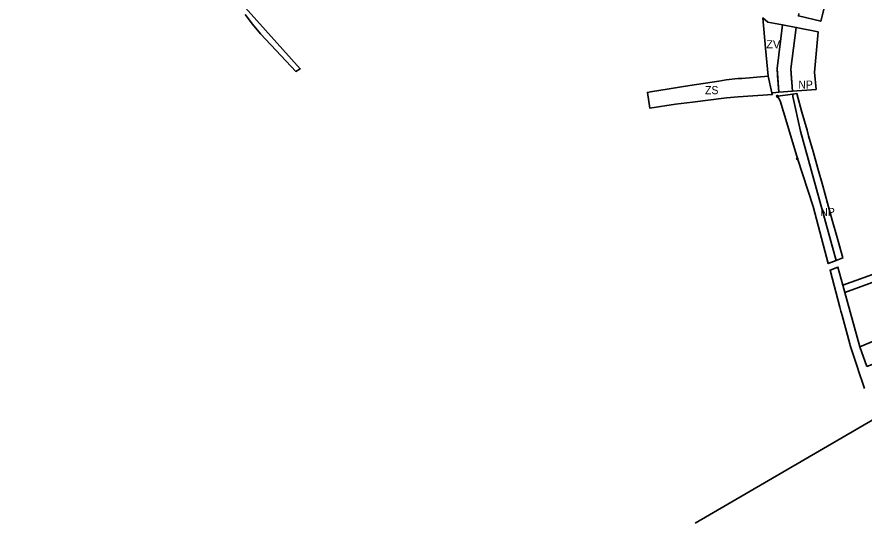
# Model space of a CAD drawing. Extents: x -650276 to -642489, y -1074311 to -1066658.
# Drawn here: x -650258 to -649019, y -1071012 to -1070272 of the extents above; entities that cross this region are included whole.
import ezdxf

# ---------------------------------------------------------------- set-up
doc = ezdxf.new("R2010")
doc.units = 0
doc.header["$LTSCALE"] = 4.8
doc.header["$PDMODE"] = 32
doc.header["$PDSIZE"] = 2.4
for name, color, linetype, lineweight in [('24', 7, 'Continuous', 35), ('40', 7, 'Continuous', 35), ('41', 7, 'Continuous', 35), ('48', 7, 'Continuous', 35), ('54', 7, 'Continuous', 35)]:
    doc.layers.add(name, color=color, linetype=linetype, lineweight=lineweight)
doc.layers.add('62', color=7, linetype='Continuous')

msp = doc.modelspace()

# ---------------------------------------------------------------- linework, layer by layer
at = {"layer": '24'}
msp.add_line((-649146.163, -1070347.543), (-649145.424, -1070357.637), dxfattribs=at)
for points in [[(-649138.43, -1070283.6), (-649146.163, -1070347.543), (-649146.163, -1070347.543), (-649145.424, -1070357.637)], [(-649125.503, -1070355.837), (-649126.069, -1070348.097), (-649118.257, -1070287.455), (-649138.43, -1070283.6), (-649146.163, -1070347.543)], [(-649125.503, -1070355.837), (-649126.069, -1070348.097), (-649118.257, -1070287.455), (-649138.43, -1070283.6)], [(-649145.424, -1070357.637), (-649143.633, -1070382.123), (-649123.693, -1070380.572), (-649125.503, -1070355.837)], [(-649145.424, -1070357.637), (-649143.633, -1070382.123), (-649123.693, -1070380.572), (-649125.503, -1070355.837)], [(-649059.951, -1070628.223), (-649112.14, -1070439.152), (-649123.138, -1070388.16), (-649123.385, -1070384.775), (-649145.73, -1070387.91)], [(-649145.73, -1070387.91), (-649141.48, -1070394.84), (-649132.07, -1070426.81), (-649116.56, -1070479.19)], [(-649116.56, -1070479.19), (-649093.2, -1070549.1), (-649071.33, -1070632.6), (-649059.951, -1070628.223)], [(-649014.888, -1070782.994), (-649025.129, -1070754.377), (-649047.11, -1070674.743), (-649050.081, -1070663.981), (-649057.338, -1070637.689), (-649068.65, -1070642.23), (-649068.65, -1070642.23), (-649054.31, -1070696.44), (-649052.77, -1070702.25), (-649052.44, -1070703.48), (-649051.03, -1070708.74), (-649040.03, -1070750.06), (-649039.38, -1070752.51), (-649039.06, -1070753.72), (-649038.51, -1070755.38), (-649027.74, -1070787.51), (-649027.64, -1070787.8), (-649019.48, -1070812.18), (-649018.48, -1070815.18)]]:
    msp.add_lwpolyline(points, dxfattribs=at)
for p in [(-649145.73, -1070387.91), (-649116.56, -1070479.19)]:
    msp.add_point(p, dxfattribs=at)
at = {"layer": '40'}
msp.add_lwpolyline([(-649138.43, -1070283.6), (-649159.78, -1070279.52), (-649166.86, -1070273.48), (-649162.91, -1070317.47), (-649159.19, -1070358.82), (-649153.64, -1070382.9), (-649148.23, -1070382.48), (-649143.633, -1070382.123), (-649146.163, -1070347.543)], close=True, dxfattribs=at)
at = {"layer": '41'}
msp.add_lwpolyline([(-649159.19, -1070358.82), (-649197.91, -1070361.8), (-649203.4, -1070362.23), (-649220.47, -1070363.94), (-649231.39, -1070365.69), (-649273.57, -1070372.44), (-649304.18, -1070377.35), (-649331.3, -1070381.69), (-649335.79, -1070382.41), (-649332.2, -1070405.42), (-649294.79, -1070399.65), (-649269.769, -1070396.502), (-649220.16, -1070390.26), (-649202.969, -1070388.965), (-649153.11, -1070385.21), (-649153.64, -1070382.9)], close=True, dxfattribs=at)
at = {"layer": '48'}
for points in [[(-649924.15, -1070268.55), (-649913.03, -1070282.44), (-649901.59, -1070296.73), (-649871.28, -1070329.01), (-649850.04, -1070351.64), (-649843.513, -1070347.685), (-650257.713, -1069885.547)], [(-649114.172, -1070266.777), (-649114.931, -1070270.621), (-649082.233, -1070278.265), (-649036.031, -1070097.854), (-649057.722, -1070089.665), (-649067.061, -1070085.844)], [(-649089.07, -1070377.88), (-649091.46, -1070352.73), (-649086.157, -1070293.589), (-649118.257, -1070287.455), (-649126.069, -1070348.097)], [(-649126.069, -1070348.097), (-649123.693, -1070380.572), (-649089.07, -1070377.88)]]:
    msp.add_lwpolyline(points, dxfattribs=at)
for points in [[(-649059.951, -1070628.223), (-649049.96, -1070624.38), (-649055.93, -1070603.08), (-649058.38, -1070594.33), (-649065.42, -1070569.21), (-649072.47, -1070544.09), (-649079.51, -1070518.97), (-649086.55, -1070493.85), (-649093.59, -1070468.73), (-649100.01, -1070445.82), (-649102.31, -1070437.61), (-649109.76, -1070411.05), (-649117.36, -1070383.93), (-649123.385, -1070384.775), (-649123.138, -1070388.16), (-649112.14, -1070439.152)], [(-649014.888, -1070782.994), (-648966.35, -1070764.7), (-648908.94, -1070740.19), (-648892.215, -1070733.293), (-648927.2, -1070637.98), (-648941.064, -1070599.735), (-648965.569, -1070610.382), (-648956.687, -1070630.825), (-649050.081, -1070663.981), (-649047.11, -1070674.743), (-648952.455, -1070640.564), (-648922.196, -1070710.207), (-648924.668, -1070712.022), (-648943.837, -1070720.104), (-649025.129, -1070754.377)]]:
    msp.add_lwpolyline(points, close=True, dxfattribs=at)
at = {"layer": '54'}
msp.add_line((-649003.638, -1070859.543), (-649266.084, -1071012.071), dxfattribs=at)

# ---------------------------------------------------------------- texts
at = {"layer": '62'}
msp.add_text('ZV', height=12, dxfattribs=at).set_placement((-649162.076, -1070318.026))
at = {"layer": '62', "width": 0.95}
for s, p in [('ZS', (-649251.482, -1070385.05)), ('NP', (-649115.076, -1070377.026)), ('NP', (-649082.942, -1070563.157))]:
    msp.add_text(s, height=12, dxfattribs=at).set_placement(p)

doc.saveas('drawing.dxf')
